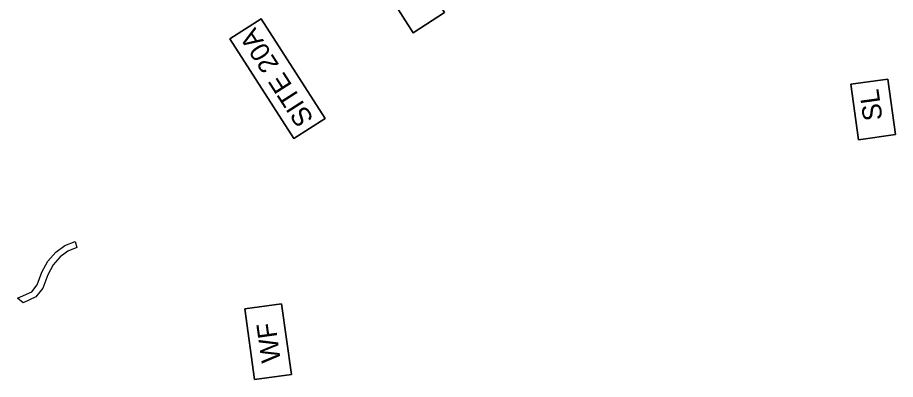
# Model space of a CAD drawing. Extents: x 474218 to 481634, y 484357 to 504997.
# Drawn here: x 477452 to 478138, y 498964 to 499247 of the extents above; entities that cross this region are included whole.
import ezdxf

# ---------------------------------------------------------------- set-up
doc = ezdxf.new("R2010")
doc.units = 0
for name, color, linetype in [('Default', 7, 'Continuous'), ('Exist Hydro Jurisdictional Stream or Body of Water', 7, 'Continuous'), ('Old_Level_29', 7, 'Continuous'), ('Old_Level_30', 7, 'Continuous'), ('Prop Grid Mask', 7, 'Continuous'), ('Scratch_Level_4', 7, 'Continuous')]:
    doc.layers.add(name, color=color, linetype=linetype)

msp = doc.modelspace()

# ---------------------------------------------------------------- linework, layer by layer
at = {"layer": 'Default'}
msp.add_line((477456.88, 499023.86), (477452.39, 499027.31), dxfattribs=at)
at = {"layer": 'Exist Hydro Jurisdictional Stream or Body of Water'}
for points in [[(477761.5, 499235.07), (477737.89, 499271.87), (477762.37, 499287.58), (477785.98, 499250.77)], [(478109.39, 499151.37), (478103.37, 499194.69), (478132.17, 499198.69), (478138.2, 499155.38)]]:
    msp.add_lwpolyline(points, close=True, dxfattribs=at)
at = {"layer": 'Old_Level_29'}
msp.add_lwpolyline([(477668.24, 499152.3), (477618.21, 499230.29), (477642.7, 499245.99), (477692.73, 499168.01)], close=True, dxfattribs=at)
at = {"layer": 'Old_Level_30'}
msp.add_lwpolyline([(477637.54, 498963.8), (477629.85, 499019.05), (477658.65, 499023.06), (477666.34, 498967.81)], close=True, dxfattribs=at)
at = {"layer": 'Prop Grid Mask'}
for points in [[(477785.98, 499250.77), (477762.37, 499287.58), (477737.89, 499271.87), (477761.5, 499235.07)], [(477692.73, 499168.01), (477642.7, 499245.99), (477618.21, 499230.29), (477668.24, 499152.3)], [(478138.2, 499155.38), (478132.17, 499198.69), (478103.37, 499194.69), (478109.39, 499151.37)], [(477666.34, 498967.81), (477658.65, 499023.06), (477629.85, 499019.05), (477637.54, 498963.8)]]:
    msp.add_lwpolyline(points, close=True, dxfattribs=at)
at = {"layer": 'Scratch_Level_4'}
msp.add_lwpolyline([(477498.6, 499066.91), (477491.69, 499064.08), (477489.7, 499062.59), (477485.8, 499059.69), (477480.12, 499053.37), (477475.99, 499045.62), (477472.19, 499035.24), (477470.02, 499032.5), (477466.71, 499028.32), (477456.88, 499023.86), (477452.39, 499027.31), (477463.54, 499032.37), (477467.78, 499037.72), (477471.42, 499047.66), (477475.99, 499056.25), (477482.41, 499063.41), (477489.21, 499068.46), (477497.29, 499071.78)], close=True, dxfattribs=at)

# ---------------------------------------------------------------- texts
at = {"layer": 'Exist Hydro Jurisdictional Stream or Body of Water'}
msp.add_text('SL', height=15, rotation=97.92303, dxfattribs=at).set_placement((478128.21, 499167.23))
at = {"layer": 'Old_Level_29'}
msp.add_text('SITE 20A', height=15, rotation=122.68216, dxfattribs=at).set_placement((477684.18, 499167.61))
at = {"layer": 'Old_Level_30'}
msp.add_text('WF', height=15, rotation=97.92303, dxfattribs=at).set_placement((477658.01, 498978.11))

doc.saveas('drawing.dxf')
